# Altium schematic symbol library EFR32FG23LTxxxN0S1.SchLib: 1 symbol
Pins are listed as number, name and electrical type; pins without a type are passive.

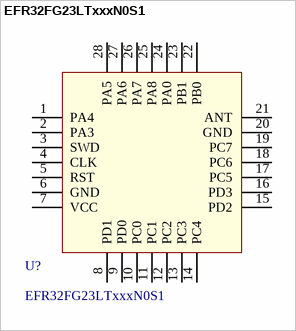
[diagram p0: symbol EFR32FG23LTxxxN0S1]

## EFR32FG23LTxxxN0S1
designator U?
pins: 1 PA4, 2 PA3, 3 SWD, 4 CLK, 5 RST, 6 GND, 7 VCC, 8 PD1, 9 PD0, 10 PC0, 11 PC1, 12 PC2, 13 PC3, 14 PC4, 15 PD2, 16 PD3, 17 PC5, 18 PC6, 19 PC7, 20 GND, 21 ANT, 22 PB0, 23 PB1, 24 PA0, 25 PA8, 26 PA7, 27 PA6, 28 PA5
